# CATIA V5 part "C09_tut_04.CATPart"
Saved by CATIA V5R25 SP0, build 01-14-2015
Part number: Part1
Bounding box of the stored display mesh (mm): x -112.5 to 112.5, y -202.5 to 80, z -202.5 to 85
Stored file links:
  E:\ashutosh\Academics\Catia\CATIA V5-6R2013_partfiles\Tutorials_ver_2\C09_tut_04.CATPart
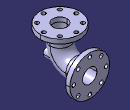
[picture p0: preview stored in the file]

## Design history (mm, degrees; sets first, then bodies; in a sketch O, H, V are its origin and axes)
Body1 (main body)
  Sketch1 on yz-plane, origin (0, 0, 0), H (0, 1, 0), V (0, 0, 1)
    line L1 (-90, 60) -> (-90, 0)
    point P1 (-90, 60)
    arc A1 centre (0, 0) radius 90 from (-90, 0) to (0, -90) ccw
    point P3 (0, 0)
    line L2 (0, -90) -> (55, -90)
    point P5 (55, -90)
    distance P1 L2 = 150
    distance P5 L1 = 145
    radius A1 = 90
    vertical: L1 V
    tangency: A1 L1, L2 A1
    horizontal: L2 H
    coincidence: P3 O
  Plane1: type Normal, Curve Sketch1, RefPoint Sketch1.P5, Ratio 0
  Sketch2 on Plane1, origin (0, 55, 0), H (-1, 0, 0), V (0, 0, 1)
    circle A1 centre (0, -90) radius 48.5
    point P1 (0, -90)
    reference projected point E1 (0, -90) from Sketch1.P5
    radius A1 = 48.5
    coincidence: P1 V, P1 E1
  Rib1: profile Sketch2, centre curve Sketch1, thin wall 16
  Sketch3 on face of Rib1, origin (0, 55, 0), H (-1, 0, 0), V (0, 0, 1)
    circle A1 centre (0, -90) radius 112.5
    point P1 (0, -90)
    reference projected circle E1 centre (0, -90) radius 56.5 from edge [face of Rib1 | face of Rib1]
    circle A2 centre (0, -90) radius 40.5
    reference projected circle E2 centre (0, -90) radius 40.5 from edge [face of Rib1 | face of Rib1]
    radius A1 = 112.5
    coincidence: P1 V, A2 E2
    concentricity: A1 E1
  Pad1: profile Sketch3, direction (0, 1, 0), length 25
  Sketch4 on face of Rib1, origin (0, 0, 60), H (1, 0, 0), V (0, 1, 0)
    circle A1 centre (0, -90) radius 112.5
    point P1 (0, -90)
    reference projected circle E1 centre (0, -90) radius 56.5 from edge [face of Rib1 | face of Rib1]
    circle A2 centre (0, -90) radius 40.5
    reference projected circle E2 centre (0, -90) radius 40.5 from edge [face of Rib1 | face of Rib1]
    radius A1 = 112.5
    coincidence: P1 V, A2 E2
    concentricity: A1 E1
  Pad2: profile Sketch4, direction (0, 0, 1), length 25
  Plane2: type Offset, RefPlane end face of Pad1, Offset 240
  Sketch5 on Plane2, origin (0, -160, 0), H (-1, 0, 0), V (0, 0, 1)
    circle A1 centre (0, -90) radius 25
    point P1 (0, -90)
    reference projected line E1 (-112.5, 85) -> (112.5, 85) from edge [face of Pad2 from Sketch4.A1 | end face of Pad2]
    radius A1 = 25
    distance E1 P1 = 175
    coincidence: P1 V
  Pad3: profile Sketch5, direction (0, 1, 0), up to the existing solid (limit type 2)
  Point1: type Center, Curve edge [start face of Pad3 | face of Pad3 from Sketch5.A1]
  Sketch6 on start face of Pad3, origin (0, -160, -90), H (1, 0, 0), V (0, 0, 1)
    point P1 (0, 0)
    reference projected point E1 (0, 0) from Point1
    coincidence: E1 P1
  Hole1: placed by Sketch6, at (0, -160, -90) direction (0, 1, 0), diameter 20, through (limit type 6), counterbore diameter 24, counterbore depth 28
  Sketch7 on end face of Pad1, origin (0, 80, 0), H (-1, 0, 0), V (0, 0, 1)
    construction circle A1 centre (0, -90) radius 92.5
    point P1 (0, -90)
    reference projected circle E1 centre (0, -90) radius 112.5 from edge [face of Pad1 from Sketch3.A1 | end face of Pad1]
    point P2 (0, 2.5)
    radius A1 = 92.5
    coincidence: P1 V, P2 A1, P2 V
    concentricity: A1 E1
  Sketch8 on end face of Pad1, origin (0, 80, 2.5), H (1, 0, 0), V (0, 0, -1)
    point P1 (0, 0)
    reference projected point E1 (0, 0) from Sketch7.P2
    coincidence: E1 P1
  Hole2: placed by Sketch8, at (0, 80, 2.5) direction (0, -1, 0), diameter 20.5, through (limit type 6)
  CircPattern1: of Hole2, instances 8, angular step 45 {= 360.0*1 deg/CircPattern1.AngularNumber}, axis from face of Pad1
  Sketch9 on end face of Pad2, origin (0, 0, 85), H (1, 0, 0), V (0, 1, 0)
    construction circle A1 centre (0, -90) radius 92.5
    point P1 (0, -90)
    reference projected circle E1 centre (0, -90) radius 112.5 from edge [face of Pad2 from Sketch4.A1 | end face of Pad2]
    point P2 (0, 2.5)
    radius A1 = 92.5
    coincidence: P1 V, P2 A1, P2 V
    concentricity: A1 E1
  Sketch10 on end face of Pad2, origin (0, 2.5, 85), H (1, 0, 0), V (0, 1, 0)
    point P1 (0, 0)
    reference projected point E1 (0, 0) from Sketch9.P2
    coincidence: E1 P1
  Hole3: placed by Sketch10, at (0, 2.5, 85) direction (0, 0, -1), diameter 20.5, through (limit type 6)
  CircPattern2: of Hole3, instances 8, angular step 45 {= 360.0*1 deg/CircPattern2.AngularNumber}, axis from face of Pad2 from Sketch4.A2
